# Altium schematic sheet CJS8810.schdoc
size 127 x 101 mm
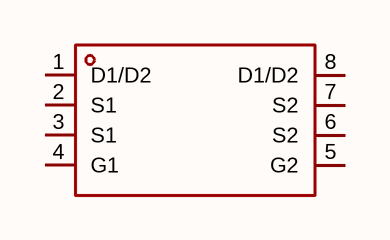
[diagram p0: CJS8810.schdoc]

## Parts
Q?  cjs8810  [TSSOP-8_L4.4-W3.0-P0.65-LS6.4-BL]  (value not drawn)

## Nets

Not connected (* = marked no-connect by the designer): Q? 1(D1/D2) 2(S1) 3(S1) 4(G1) 5(G2) 6(S2) 7(S2) 8(D1/D2)

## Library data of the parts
Q? = cjs8810: 数量:2个N沟道;漏源电压(Vdss):20V;连续漏极电流(Id):7A;导通电阻(RDS(on)):26mΩ@1.8V;耗散功率(Pd):-;阈值电压(Vgs(th)):400mV;; Manufacturer: CJ(江苏长电/长晶); AddInBom: yes; ModelId: 85577802f9634e7e85ffa2fd25a37b6f; ModelName: TSSOP-8_L4.4-W3.0-P0.65-LS6.4-BL-2; ModelTransform: 118.11,251.968,0,0,0,0,0,0,0; Number: 2个N沟道; Drain to Source Voltage: 20V; Current - Continuous Drain(Id): 7A; Gate Threshold Voltage (Vgs(th)): 400mV; Gate Charge(Qg): 15nC@4.5V; Input Capacitance(Ciss): 1.15nF; Reverse Transfer Capacitance (Crss@Vds): 145pF; Type: N沟道; Output Capacitance(Coss): 185pF; Vgs: ±12V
